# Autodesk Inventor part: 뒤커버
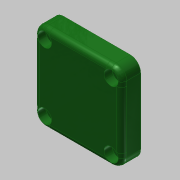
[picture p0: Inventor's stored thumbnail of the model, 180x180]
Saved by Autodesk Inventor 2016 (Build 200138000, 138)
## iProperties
Created: 2018-07
Part Number: 뒤커버
Material: 알루미늄 6061
Document SubType Name: Modeling
Designer: mduedu
Density: 1 g/cm^3
Appearance: 매끄러움 - 짙은 산림 녹색
Author: mduedu
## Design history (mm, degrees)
sketch "스케치1"
  geometry: C1 r 16 at (0, 0); 1 further point
  constraints: 1 centre point, 1 coincident
  dimensions: "d0" = 32 diameter of C1
extrude "돌출1" new body sketch "스케치1" distance "d1" = 3; taper "d2" = 0 deg
sketch "스케치2"
  geometry: L1 (-25, -25)-(25, -25); L2 (25, -25)-(25, 25); L3 (25, 25)-(-25, 25); L4 (-25, 25)-(-25, -25); L5 (-25, -25)-(25, 25); L6 (25, -25)-(-25, 25); 1 further point
  constraints: 12 end point, 2 midpoint, 2 parallel, 1 horizontal, 1 perpendicular
  dimensions: "d3" = 50 distance of L3.end L2.end; "d4" = 50 distance of L2.end L1.end
extrude "돌출2" join sketch "스케치2" distance "d5" = 11; taper "d6" = 0 deg
hole "구멍1" diameter "d9" = 25; stored, may be unused: countersink angle "d13" = 90 deg, drill point angle "d15" = 0 deg; dims "d7" = 10, "d8" = 10, "d10" = 6, "d11" = 4, "d12" = 2, "d14" = 3
fillet "모깎기2" dims "d26" = 3
fillet "모깎기3" dims "d27" = 6
sketch "스케치5"
  geometry: L1 (25, -19)-(25, 19) reference; L2 (19, 25)-(-19, 25) reference; L3 (-25, 19)-(-25, -19) reference; L4 (-19, -25)-(19, -25) reference; A1 r 6 centre (19, -19) between (19, -25) and (25, -19) reference; A2 r 6 centre (19, 19) between (25, 19) and (19, 25) reference; A3 r 6 centre (-19, 19) between (-19, 25) and (-25, 19) reference; A4 r 6 centre (-19, -19) between (-25, -19) and (-19, -25) reference; 5 further points
  constraints: 4 coincident
hole "구멍2" sketch "스케치5" at (-19, 19), (19, 19), (19, -19), (-19, -19) diameter "d28" = 4.5; stored, may be unused: countersink angle "d32" = 90 deg, drill point angle "d34" = 0 deg; dims "d29" = 6, "d30" = 8, "d31" = 4.6, "d33" = 3
fillet "모깎기4" dims "d35" = 3
chamfer "모따기2" distance "d36" = 1; stored, may be unused: second distance "d37" = 2, angle "d38" = 45 deg
node "솔리드1"
node "투영된 루프1"
